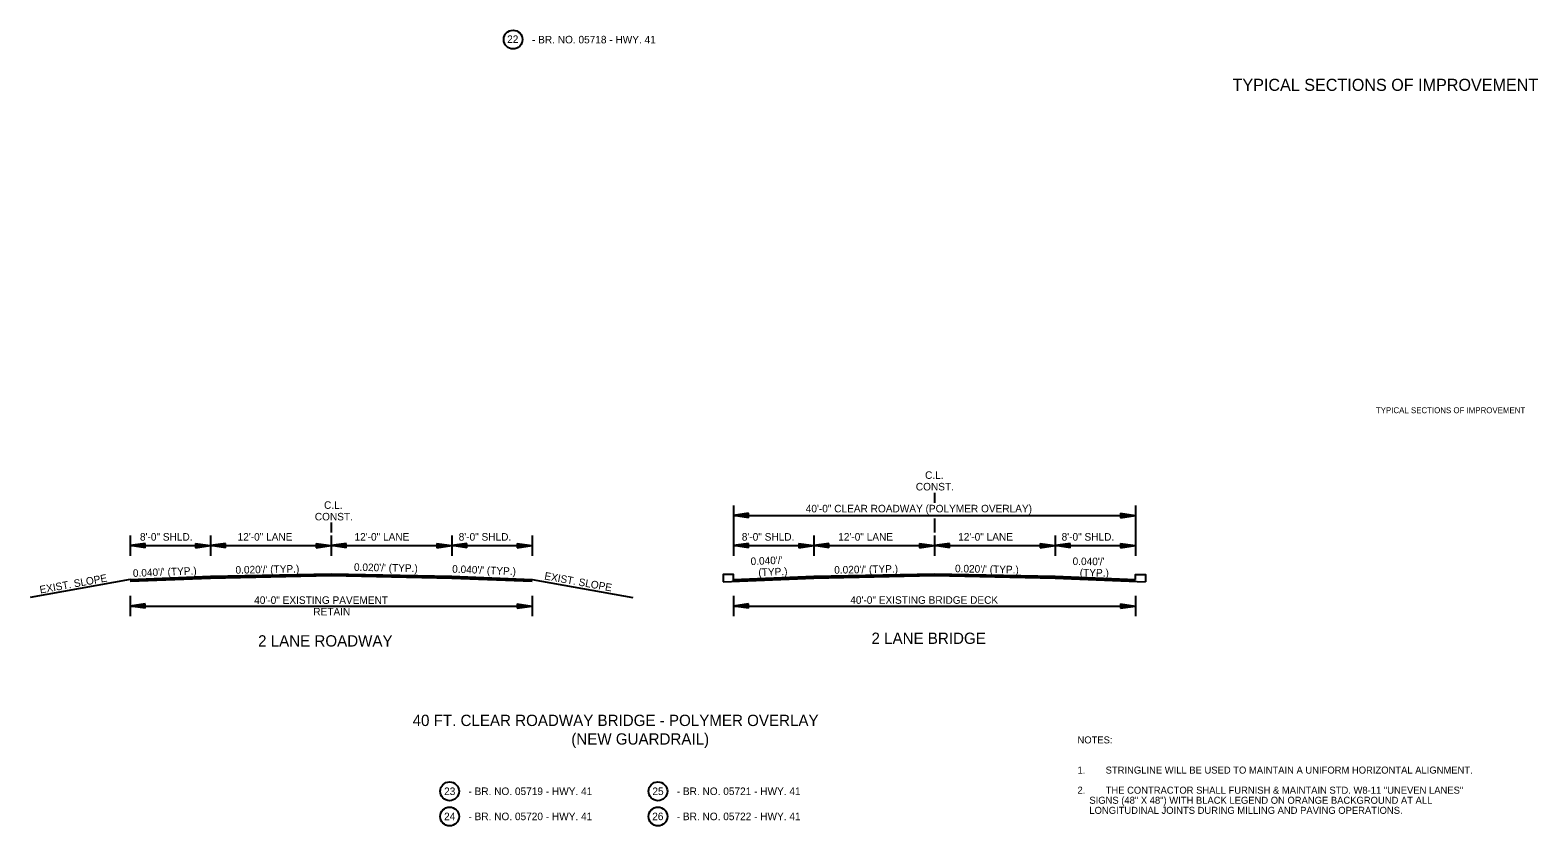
# Model space of a CAD drawing. Extents: x 545241 to 1930787, y -1971772 to 596640.
# Drawn here: x 546768 to 548268, y -1959502 to -1958711 of the extents above; entities that cross this region are included whole.
import ezdxf

# ---------------------------------------------------------------- set-up
doc = ezdxf.new("R2010")
doc.units = 0
for name, color, linetype in [('R_Border', 7, 'Continuous'), ('R_Border Notes', 7, 'Continuous'), ('R_Border Prem', 7, 'Continuous'), ('R_Draft', 7, 'Continuous')]:
    doc.layers.add(name, color=color, linetype=linetype)

# ---------------------------------------------------------------- blocks, each defined once
blk = doc.blocks.new('ARROW')
at = {"layer": 'R_Draft'}
for p, q in [((-2, 0.3), (0, 0)), ((-2, 0.3), (-2, -0.3)), ((-2, 0.25), (-0.334, 0)), ((-2, 0.199), (-0.678, 0)), ((-2, 0.149), (-1.011, 0)), ((-2, 0.097), (-1.35, 0)), ((-2, 0.047), (-1.684, 0)), ((-2, -0.3), (0, 0)), ((-2, -0.098), (-1.35, 0)), ((-2, -0.199), (-0.678, 0)), ((-2, -0.25), (-0.334, 0)), ((-2, -0.149), (-1.011, 0)), ((-2, -0.047), (-1.684, 0))]:
    blk.add_line(p, q, dxfattribs=at)

msp = doc.modelspace()

# ---------------------------------------------------------------- linework, layer by layer
at = {"layer": 'R_Border'}
for p, q in [((547467.7, -1959183.7), (547467.7, -1959233.7)), ((547667.7, -1959171.2), (547667.7, -1959181.2)), ((547867.7, -1959183.7), (547867.7, -1959233.7)), ((547467.7, -1959193.7), (547867.7, -1959193.7)), ((547667.7, -1959196.7), (547667.7, -1959210.7)), ((546867.7, -1959213.7), (546867.7, -1959233.7)), ((546947.7, -1959213.7), (546947.7, -1959233.7)), ((547067.7, -1959200.7), (547067.7, -1959210.7)), ((547067.7, -1959213.7), (547067.7, -1959233.7)), ((547187.7, -1959213.7), (547187.7, -1959233.7)), ((547267.7, -1959213.7), (547267.7, -1959233.7)), ((547547.7, -1959213.7), (547547.7, -1959233.7)), ((547667.7, -1959213.7), (547667.7, -1959233.7)), ((547787.7, -1959213.7), (547787.7, -1959233.7)), ((546867.7, -1959223.7), (547267.7, -1959223.7)), ((547467.7, -1959223.7), (547867.7, -1959223.7)), ((546867.7, -1959257.3), (546768.3, -1959275.3)), ((547267.7, -1959257.3), (547367.7, -1959275.3)), ((546867.7, -1959273.7), (546867.7, -1959293.7)), ((547267.7, -1959273.7), (547267.7, -1959293.7)), ((547467.7, -1959273.7), (547467.7, -1959293.7)), ((547867.7, -1959273.7), (547867.7, -1959293.7)), ((546867.7, -1959283.7), (547267.7, -1959283.7)), ((547467.7, -1959283.7), (547867.7, -1959283.7))]:
    msp.add_line(p, q, dxfattribs=at)
for points in [[(546867.7, -1959257.3), (546947.7, -1959254.1), (547067.7, -1959251.7), (547187.7, -1959254.1), (547267.7, -1959257.3)], [(546867.7, -1959257.6), (546947.7, -1959254.4), (547067.7, -1959252), (547187.7, -1959254.4), (547267.7, -1959257.6)], [(546867.7, -1959257.9), (546947.7, -1959254.7), (547067.7, -1959252.3), (547187.7, -1959254.7), (547267.7, -1959257.9)], [(546867.7, -1959258.2), (546947.7, -1959255), (547067.7, -1959252.6), (547187.7, -1959255), (547267.7, -1959258.2)], [(546867.7, -1959258.5), (546947.7, -1959255.3), (547067.7, -1959252.9), (547187.7, -1959255.3), (547267.7, -1959258.5)], [(546867.7, -1959258.8), (546947.7, -1959255.6), (547067.7, -1959253.2), (547187.7, -1959255.6), (547267.7, -1959258.8)], [(546867.7, -1959259.1), (546947.7, -1959255.9), (547067.7, -1959253.5), (547187.7, -1959255.9), (547267.7, -1959259.1)], [(547467.7, -1959258.8), (547467.7, -1959252.3), (547457.7, -1959252.3), (547457.7, -1959259.5)], [(547457.7, -1959259.5), (547547.7, -1959255.9), (547667.7, -1959253.5), (547787.7, -1959255.9), (547877.7, -1959259.5)], [(547467.7, -1959257.3), (547547.7, -1959254.1), (547667.7, -1959251.7), (547787.7, -1959254.1), (547867.7, -1959257.3)], [(547467.7, -1959257.6), (547547.7, -1959254.4), (547667.7, -1959252), (547787.7, -1959254.4), (547867.7, -1959257.6)], [(547467.7, -1959257.9), (547547.7, -1959254.7), (547667.7, -1959252.3), (547787.7, -1959254.7), (547867.7, -1959257.9)], [(547467.7, -1959258.2), (547547.7, -1959255), (547667.7, -1959252.6), (547787.7, -1959255), (547867.7, -1959258.2)], [(547467.7, -1959258.5), (547547.7, -1959255.3), (547667.7, -1959252.9), (547787.7, -1959255.3), (547867.7, -1959258.5)], [(547467.7, -1959258.8), (547547.7, -1959255.6), (547667.7, -1959253.2), (547787.7, -1959255.6), (547867.7, -1959258.8)], [(547867.7, -1959257.3), (547867.7, -1959252.3), (547877.7, -1959252.3), (547877.7, -1959259.5)]]:
    msp.add_lwpolyline(points, dxfattribs=at)
for centre in [(547248.6, -1958720.6), (547185.5, -1959467.9), (547392.7, -1959467.9), (547185.5, -1959492.9), (547392.7, -1959492.9)]:
    msp.add_circle(centre, 9.34, dxfattribs=at)

# ---------------------------------------------------------------- block references
at = {"layer": 'R_Border', "xscale": 7.5, "yscale": 7.5, "rotation": 180}
for p in [(547467.7, -1959193.7), (546867.7, -1959223.7), (546947.7, -1959223.7), (547067.7, -1959223.7), (547187.7, -1959223.7), (547467.7, -1959223.7), (547547.7, -1959223.7), (547667.7, -1959223.7), (547787.7, -1959223.7), (546867.7, -1959283.7), (547467.7, -1959283.7)]:
    msp.add_blockref('ARROW', p, dxfattribs=at)
at = {"layer": 'R_Border', "xscale": 7.5, "yscale": 7.5}
for p in [(547867.7, -1959193.7), (546947.7, -1959223.7), (547067.7, -1959223.7), (547187.7, -1959223.7), (547267.7, -1959223.7), (547547.7, -1959223.7), (547667.7, -1959223.7), (547787.7, -1959223.7), (547867.7, -1959223.7), (547267.7, -1959283.7), (547867.7, -1959283.7)]:
    msp.add_blockref('ARROW', p, dxfattribs=at)

# ---------------------------------------------------------------- texts
at = {"layer": 'R_Border'}
for s, height, rotation, p in [('TYPICAL SECTIONS OF IMPROVEMENT', 12, 360, (547964.2, -1958771.6)), ("0.040'/' (TYP.)", 7.5, 2.2916, (546870.6, -1959254.8)), ("0.020'/' (TYP.)", 7.5, 1.1458, (546972.6, -1959251.6)), ("0.020'/' (TYP.)", 7.5, 358.8542, (547090.3, -1959248.7)), ("0.040'/' (TYP.)", 7.5, 357.7084, (547187.9, -1959250.5)), ("0.040'/'", 7.5, 2.2916, (547485, -1959243)), ('(TYP.)', 7.5, 2.2916, (547492.7, -1959254)), ("0.020'/' (TYP.)", 7.5, 1.1458, (547568.1, -1959251.6)), ("0.020'/' (TYP.)", 7.5, 358.8542, (547688.1, -1959250.1)), ("0.040'/'", 7.5, 359.3923, (547805.1, -1959242.9)), ('EXIST. SLOPE', 7.5, 10.204, (546778.4, -1959271.3)), ('EXIST. SLOPE', 7.5, 349.796, (547279.3, -1959257.2)), ('(TYP.)', 7.5, 359.3923, (547812.2, -1959254.2))]:
    msp.add_text(s, height=height, rotation=rotation, dxfattribs=at).set_placement(p)
for s, height, p in [('C.L.', 7.5, (547658.4, -1959157.3)), ('CONST.', 7.5, (547649.2, -1959168.8)), ('C.L.', 7.5, (547060.6, -1959187.1)), ('40\'-0" CLEAR ROADWAY (POLYMER OVERLAY)', 7.5, (547539.7, -1959190.6)), ('CONST.', 7.5, (547051.4, -1959198.6)), ('8\'-0" SHLD.', 7.5, (546877.5, -1959218.7)), ('12\'-0" LANE', 7.5, (546974.6, -1959218.7)), ('12\'-0" LANE', 7.5, (547090.9, -1959218.7)), ('8\'-0" SHLD.', 7.5, (547194.5, -1959218.7)), ('8\'-0" SHLD.', 7.5, (547476.1, -1959218.7)), ('12\'-0" LANE', 7.5, (547572, -1959218.7)), ('12\'-0" LANE', 7.5, (547691.3, -1959218.7)), ('8\'-0" SHLD.', 7.5, (547794.2, -1959218.7)), ('40\'-0" EXISTING PAVEMENT', 7.5, (546991.1, -1959281.6)), ('40\'-0" EXISTING BRIDGE DECK', 7.5, (547584, -1959281.5)), ('RETAIN', 7.5, (547049.9, -1959293.1)), ('2 LANE ROADWAY', 11.25, (546995, -1959324)), ('2 LANE BRIDGE', 11.25, (547605.1, -1959321.4)), ('40 FT. CLEAR ROADWAY BRIDGE - POLYMER OVERLAY', 11.25, (547148.7, -1959403)), ('(NEW GUARDRAIL)', 11.25, (547306.5, -1959421.5))]:
    msp.add_text(s, height=height, dxfattribs=at).set_placement(p)
at = {"layer": 'R_Border Notes'}
for s, p in [('NOTES: ', (547810, -1959420.3)), ('1.', (547810, -1959450.3)), ('STRINGLINE WILL BE USED TO MAINTAIN A UNIFORM HORIZONTAL ALIGNMENT.', (547838, -1959450.3)), ('2.', (547810, -1959470.3)), ('THE CONTRACTOR SHALL FURNISH & MAINTAIN STD. W8-11 "UNEVEN LANES" ', (547838, -1959470.3)), ('    SIGNS (48" X 48") WITH BLACK LEGEND ON ORANGE BACKGROUND AT ALL ', (547811.4, -1959480.3)), ('    LONGITUDINAL JOINTS DURING MILLING AND PAVING OPERATIONS.', (547811.4, -1959490.3))]:
    msp.add_text(s, height=7, dxfattribs=at).set_placement(p)
at = {"layer": 'R_Border Prem'}
msp.add_text('TYPICAL SECTIONS OF IMPROVEMENT', height=5.862, rotation=360, dxfattribs=at).set_placement((548106.8, -1959092))
at = {"layer": 'R_Draft'}
for s, p in [('22', (547242.7, -1958724)), ('- BR. NO. 05718 - HWY. 41', (547267.4, -1958724.4)), ('23', (547180, -1959471.6)), ('- BR. NO. 05719 - HWY. 41', (547204.2, -1959471.6)), ('25', (547387.2, -1959471.6)), ('- BR. NO. 05721 - HWY. 41', (547411.4, -1959471.6)), ('24', (547180, -1959496.6)), ('- BR. NO. 05720 - HWY. 41', (547204.2, -1959496.6)), ('26', (547387, -1959496.6)), ('- BR. NO. 05722 - HWY. 41', (547411.4, -1959496.6))]:
    msp.add_text(s, height=7.5, dxfattribs=at).set_placement(p)

doc.saveas('drawing.dxf')
